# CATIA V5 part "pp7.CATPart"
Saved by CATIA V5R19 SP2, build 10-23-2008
Part number: pp7
Publications: "Line.1", "Line.4", "Point.4", "Plane.2"
Bounding box of the stored display mesh (mm): x 0 to 20, y -100 to 100, z -50 to 50
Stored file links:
  C:\Users\Welcome\Documents\thinkm2\pp7.CATPart
  C:\Users\Welcome\Documents\thinkm2\Brasmeca.CATProduct
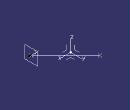
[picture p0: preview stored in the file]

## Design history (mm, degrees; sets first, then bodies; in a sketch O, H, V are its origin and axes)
AxisSystem1: origin (0, 0, 0), X (1, 0, 0), Y (0, 1, 0), Z (0, 0, 1)
Set1
  Point1: linked copy from another document
  Point2: linked copy from another document
Body1 (main body)
  Line1: type PtDir, RefPoint Point1, Direction edge [XY plane of AxisSystem1 | ZX plane of AxisSystem1], Start 0, End 20
  Point3: type OnCurve, Support Line1, Length 15
  Plane1: type Normal, Curve Line1, RefPoint Point3
  Line2: type PtPt, FirstPoint Point3, SecondPoint Point2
